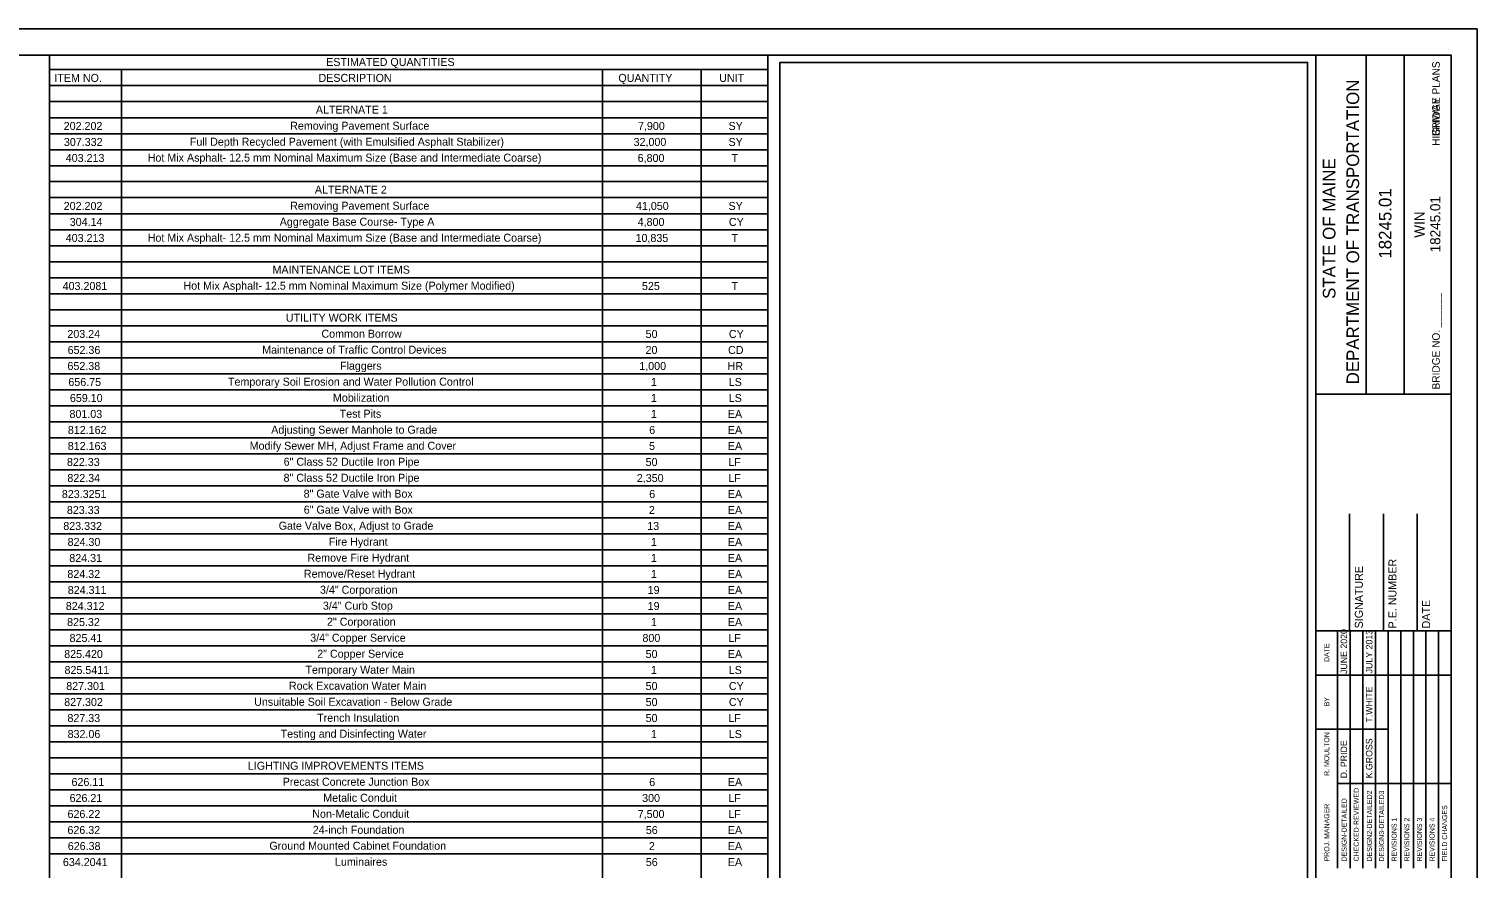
# Model space of a CAD drawing. Extents: x -0.13 to 2.7, y -0.05 to 1.78.
# Drawn here: x 0.917 to 2.698, y 0.75 to 1.782 of the extents above; entities that cross this region are included whole.
import ezdxf

# ---------------------------------------------------------------- set-up
doc = ezdxf.new("R2010")
doc.units = 0
for name, color, linetype in [('ANNOTATION', 7, 'Continuous'), ('BORDER', 7, 'Continuous'), ('BRIDGE_TITLE', 7, 'Continuous'), ('Default', 7, 'Continuous'), ('HIGHWAY_TITLE', 7, 'Continuous'), ('PLOT BOUNDARY', 7, 'Continuous')]:
    doc.layers.add(name, color=color, linetype=linetype)

msp = doc.modelspace()

# ---------------------------------------------------------------- linework, layer by layer
at = {"layer": 'BORDER'}
for p, q in [((2.5, 0), (2.5, 1.75)), ((2.5621, 1.3333), (2.5621, 1.75)), ((2.6087, 1.3333), (2.6087, 1.75)), ((0.9428, 1.7323), (1.8261, 1.7323)), ((1.0314, 1.7323), (1.0314, 0)), ((1.6227, 1.7323), (1.6227, 0)), ((1.7441, 1.7323), (1.7441, 0)), ((0.9428, 1.7126), (1.8261, 1.7126)), ((0.9428, 1.6929), (1.8261, 1.6929)), ((0.9428, 1.6732), (1.8261, 1.6732)), ((0.9428, 1.6535), (1.8261, 1.6535)), ((0.9428, 1.6338), (1.8261, 1.6338)), ((0.9428, 1.6141), (1.8261, 1.6141)), ((0.9428, 1.5945), (1.8261, 1.5945)), ((0.9428, 1.5748), (1.8261, 1.5748)), ((0.9428, 1.5551), (1.8261, 1.5551)), ((0.9428, 1.5354), (1.8261, 1.5354)), ((0.9428, 1.5157), (1.8261, 1.5157)), ((0.9428, 1.496), (1.8261, 1.496)), ((0.9428, 1.4763), (1.8261, 1.4763)), ((0.9428, 1.4566), (1.8261, 1.4566)), ((0.9428, 1.437), (1.8261, 1.437)), ((0.9428, 1.4173), (1.8261, 1.4173)), ((0.9428, 1.3976), (1.8261, 1.3976)), ((0.9428, 1.3779), (1.8261, 1.3779)), ((0.9428, 1.3582), (1.8261, 1.3582)), ((0.9428, 1.3385), (1.8261, 1.3385)), ((0.9428, 1.3188), (1.8261, 1.3188)), ((2.5, 1.3332), (2.6667, 1.3332)), ((0.9428, 1.2992), (1.8261, 1.2992)), ((0.9428, 1.2795), (1.8261, 1.2795)), ((0.9428, 1.2598), (1.8261, 1.2598)), ((0.9428, 1.2401), (1.8261, 1.2401)), ((0.9428, 1.2204), (1.8261, 1.2204)), ((0.9428, 1.2007), (1.8261, 1.2007)), ((0.9428, 1.181), (1.8261, 1.181)), ((2.5417, 1.0417), (2.5417, 1.1858)), ((2.5833, 1.0417), (2.5833, 1.1858)), ((2.625, 1.0417), (2.625, 1.1858)), ((0.9428, 1.1614), (1.8261, 1.1614)), ((0.9428, 1.1417), (1.8261, 1.1417)), ((0.9428, 1.122), (1.8261, 1.122)), ((0.9428, 1.1023), (1.8261, 1.1023)), ((0.9428, 1.0826), (1.8261, 1.0826)), ((0.9428, 1.0629), (1.8261, 1.0629)), ((0.9428, 1.0432), (1.8261, 1.0432)), ((2.5, 1.0417), (2.6667, 1.0417)), ((0.9428, 1.0236), (1.8261, 1.0236)), ((0.9428, 1.0039), (1.8261, 1.0039)), ((0.9428, 0.9842), (1.8261, 0.9842)), ((0.9428, 0.9645), (1.8261, 0.9645)), ((0.9428, 0.9448), (1.8261, 0.9448)), ((0.9428, 0.9251), (1.8261, 0.9251)), ((0.9428, 0.9054), (1.8261, 0.9054)), ((0.9428, 0.8858), (1.8261, 0.8858)), ((0.9428, 0.8661), (1.8261, 0.8661)), ((0.9428, 0.8464), (1.8261, 0.8464)), ((0.9428, 0.8267), (1.8261, 0.8267)), ((0.9428, 0.807), (1.8261, 0.807)), ((0.9428, 0.7873), (1.8261, 0.7873)), ((0.9428, 0.7676), (1.8261, 0.7676))]:
    msp.add_line(p, q, dxfattribs=at)
msp.add_lwpolyline([(0, 1.75), (2.6667, 1.75), (2.6667, 0), (0, 0)], close=True, dxfattribs=at)
for points in [[(0.9428, 0), (0.9428, 1.75)], [(1.8261, 1.75), (1.8261, 0)], [(2.5269, 0.9875), (2.5269, 1.0417)], [(2.5425, 0.7501), (2.5425, 1.0417)], [(2.558, 1.0417), (2.558, 0.7501)], [(2.5735, 0.7501), (2.5735, 1.0417)], [(2.589, 0.7501), (2.589, 1.0417)], [(2.6046, 0.7501), (2.6046, 1.0417)], [(2.6201, 0.7501), (2.6201, 1.0417)], [(2.6356, 0.7501), (2.6356, 1.0417)], [(2.6512, 0.7501), (2.6512, 1.0417)], [(2.5269, 0.7501), (2.5269, 1.0299)], [(2.5, 0.9875), (2.6667, 0.9875)], [(2.5, 0.9209), (2.5269, 0.9209)], [(2.5269, 0.9209), (2.589, 0.9209)], [(2.5269, 0.8542), (2.6667, 0.8542)]]:
    msp.add_lwpolyline(points, dxfattribs=at)
at = {"layer": 'Default'}
msp.add_lwpolyline([(1.841, 0.5306), (2.49, 0.5306), (2.49, 1.7412), (1.841, 1.7412)], close=True, dxfattribs=at)
at = {"layer": 'PLOT BOUNDARY'}
msp.add_lwpolyline([(-0.1349, -0.051), (2.6984, -0.051), (2.6984, 1.7823), (-0.1349, 1.7823)], close=True, dxfattribs=at)

# ---------------------------------------------------------------- texts
at = {"layer": 'ANNOTATION'}
for s, height, p in [('202.202', 0.00984, (0.9602, 1.6581)), ('Removing Pavement Surface', 0.009843, (1.2387, 1.6584)), ('7,900', 0.00984, (1.6665, 1.6581)), ('SY', 0.00984, (1.7779, 1.6581)), ('307.332', 0.00984, (0.9604, 1.6384)), ('Full Depth Recycled Pavement (with Emulsified Asphalt Stabilizer)', 0.009843, (1.1154, 1.6387)), ('32,000', 0.00984, (1.6611, 1.6384)), ('SY', 0.00984, (1.7779, 1.6384)), ('403.213', 0.00984, (0.9627, 1.6187)), ('Hot Mix Asphalt- 12.5 mm Nominal Maximum Size (Base and Intermediate Coarse)', 0.009843, (1.0635, 1.6191)), ('6,800', 0.00984, (1.6661, 1.6187)), ('T', 0.00984, (1.7815, 1.6187)), ('202.202', 0.00984, (0.9602, 1.5597)), ('Removing Pavement Surface', 0.009843, (1.2387, 1.56)), ('41,050', 0.00984, (1.664, 1.5597)), ('SY', 0.00984, (1.7779, 1.5597)), ('304.14', 0.00984, (0.9676, 1.54)), ('Aggregate Base Course- Type A', 0.009843, (1.2259, 1.5403)), ('4,800', 0.00984, (1.6661, 1.54)), ('CY', 0.00984, (1.7783, 1.54)), ('403.213', 0.00984, (0.9627, 1.5203)), ('Hot Mix Asphalt- 12.5 mm Nominal Maximum Size (Base and Intermediate Coarse)', 0.009843, (1.0635, 1.5206)), ('10,835', 0.00984, (1.6635, 1.5203)), ('T', 0.00984, (1.7815, 1.5203)), ('403.2081', 0.00984, (0.9589, 1.4612)), ('Hot Mix Asphalt- 12.5 mm Nominal Maximum Size (Polymer Modified)', 0.009843, (1.1075, 1.4616)), ('525', 0.00984, (1.6714, 1.4612)), ('T', 0.00984, (1.7815, 1.4612)), ('203.24', 0.00984, (0.9647, 1.4022)), ('Common Borrow', 0.009843, (1.2772, 1.4025)), ('50', 0.00984, (1.6759, 1.4022)), ('CY', 0.00984, (1.7783, 1.4022)), ('652.36', 0.00984, (0.965, 1.3825)), ('Maintenance of Traffic Control Devices', 0.009843, (1.2043, 1.3828)), ('20', 0.00984, (1.6758, 1.3825)), ('CD', 0.00984, (1.7773, 1.3825)), ('652.38', 0.00984, (0.9648, 1.3628)), ('Flaggers', 0.00984, (1.3, 1.3631)), ('1,000', 0.00984, (1.6681, 1.3628)), ('HR', 0.00984, (1.7767, 1.3628)), ('Temporary Soil Erosion and Water Pollution Control', 0.009843, (1.1622, 1.3435)), ('656.75', 0.00984, (0.9659, 1.3431)), ('1', 0.00984, (1.6824, 1.3431)), ('LS', 0.00984, (1.7781, 1.3431)), ('659.10', 0.00984, (0.9678, 1.3234)), ('Mobilization', 0.009843, (1.2913, 1.3238)), ('1', 0.00984, (1.6824, 1.3234)), ('LS', 0.00984, (1.7781, 1.3234)), ('801.03', 0.00984, (0.9673, 1.3038)), ('Test Pits', 0.00984, (1.2996, 1.3041)), ('1', 0.00984, (1.6824, 1.3038)), ('EA', 0.00984, (1.777, 1.3038)), ('812.162', 0.00984, (0.9653, 1.2841)), ('Adjusting Sewer Manhole to Grade', 0.009843, (1.2154, 1.2844)), ('6', 0.00984, (1.6803, 1.2841)), ('EA', 0.00984, (1.777, 1.2841)), ('812.163', 0.00984, (0.9652, 1.2644)), ('Modify Sewer MH, Adjust Frame and Cover', 0.009843, (1.1889, 1.2647)), ('5', 0.00984, (1.6801, 1.2644)), ('EA', 0.00984, (1.777, 1.2644)), ('822.33', 0.00984, (0.9642, 1.2447)), ('6" Class 52 Ductile Iron Pipe', 0.009843, (1.2307, 1.245)), ('50', 0.00984, (1.6759, 1.2447)), ('LF', 0.00984, (1.7776, 1.2447)), ('822.34', 0.00984, (0.9647, 1.225)), ('8" Class 52 Ductile Iron Pipe', 0.009843, (1.2306, 1.2253)), ('2,350', 0.00984, (1.6651, 1.225)), ('LF', 0.00984, (1.7776, 1.225)), ('823.3251', 0.00984, (0.9579, 1.2053)), ('8" Gate Valve with Box', 0.009843, (1.2553, 1.2057)), ('6', 0.00984, (1.6803, 1.2053)), ('EA', 0.00984, (1.777, 1.2053)), ('823.33', 0.00984, (0.9641, 1.1856)), ('6" Gate Valve with Box', 0.009843, (1.2554, 1.186)), ('2', 0.00984, (1.6799, 1.1856)), ('EA', 0.00984, (1.777, 1.1856)), ('823.332', 0.00984, (0.9597, 1.166)), ('Gate Valve Box, Adjust to Grade', 0.009843, (1.2246, 1.1663)), ('13', 0.00984, (1.6779, 1.166)), ('EA', 0.00984, (1.777, 1.166)), ('824.30', 0.00984, (0.965, 1.1463)), ('Fire Hydrant', 0.009843, (1.2862, 1.1466)), ('1', 0.00984, (1.6824, 1.1463)), ('EA', 0.00984, (1.777, 1.1463)), ('824.31', 0.00984, (0.9671, 1.1266)), ('Remove Fire Hydrant', 0.009843, (1.26, 1.1269)), ('1', 0.00984, (1.6824, 1.1266)), ('EA', 0.00984, (1.777, 1.1266)), ('824.32', 0.00984, (0.9647, 1.1069)), ('Remove/Reset Hydrant', 0.009843, (1.2556, 1.1072)), ('1', 0.00984, (1.6824, 1.1069)), ('EA', 0.00984, (1.777, 1.1069)), ('824.311', 0.00984, (0.9652, 1.0872)), ('3/4" Corporation', 0.009843, (1.2754, 1.0875)), ('19', 0.00984, (1.6784, 1.0872)), ('EA', 0.00984, (1.777, 1.0872)), ('824.312', 0.00984, (0.9628, 1.0675)), ('3/4" Curb Stop', 0.009843, (1.279, 1.0679)), ('19', 0.00984, (1.6784, 1.0675)), ('EA', 0.00984, (1.777, 1.0675)), ('825.32', 0.00984, (0.9644, 1.0478)), ('2" Corporation', 0.009843, (1.284, 1.0482)), ('1', 0.00984, (1.6824, 1.0478)), ('EA', 0.00984, (1.777, 1.0478)), ('825.41', 0.00984, (0.9674, 1.0282)), ('3/4" Copper Service', 0.009843, (1.2634, 1.0285)), ('800', 0.00984, (1.672, 1.0282)), ('LF', 0.00984, (1.7776, 1.0282)), ('825.420', 0.00984, (0.9608, 1.0085)), ('2" Copper Service', 0.009843, (1.272, 1.0088)), ('50', 0.00984, (1.6759, 1.0085)), ('EA', 0.00984, (1.777, 1.0085)), ('825.5411', 0.00984, (0.9612, 0.9888)), ('Temporary Water Main', 0.009843, (1.2575, 0.9891)), ('1', 0.00984, (1.6824, 0.9888)), ('LS', 0.00984, (1.7781, 0.9888)), ('Rock Excavation Water Main', 0.009843, (1.2372, 0.9694)), ('827.301', 0.00984, (0.9633, 0.9691)), ('50', 0.00984, (1.6759, 0.9691)), ('CY', 0.00984, (1.7783, 0.9691)), ('827.302', 0.00984, (0.9608, 0.9494)), ('Unsuitable Soil Excavation - Below Grade', 0.009843, (1.1944, 0.9497)), ('50', 0.00984, (1.6759, 0.9494)), ('CY', 0.00984, (1.7783, 0.9494)), ('827.33', 0.00984, (0.9648, 0.9297)), ('Trench Insulation', 0.009843, (1.2719, 0.93)), ('50', 0.00984, (1.6759, 0.9297)), ('LF', 0.00984, (1.7776, 0.9297)), ('832.06', 0.00984, (0.965, 0.91)), ('Testing and Disinfecting Water', 0.009843, (1.227, 0.9104)), ('1', 0.00984, (1.6824, 0.91)), ('LS', 0.00984, (1.7781, 0.91)), ('626.11', 0.00984, (0.9698, 0.851)), ('Precast Concrete Junction Box', 0.009843, (1.2295, 0.8513)), ('6', 0.00984, (1.6803, 0.851)), ('EA', 0.00984, (1.777, 0.851)), ('626.21', 0.00984, (0.9674, 0.8313)), ('Metalic Conduit', 0.009843, (1.2794, 0.8316)), ('300', 0.00984, (1.6716, 0.8313)), ('LF', 0.00984, (1.7776, 0.8313)), ('626.22', 0.00984, (0.9649, 0.8116)), ('Non-Metalic Conduit', 0.009843, (1.2659, 0.8119)), ('7,500', 0.00984, (1.6662, 0.8116)), ('LF', 0.00984, (1.7776, 0.8116)), ('626.32', 0.00984, (0.9648, 0.7919)), ('24-inch Foundation', 0.009843, (1.2665, 0.7922)), ('56', 0.00984, (1.6761, 0.7919)), ('EA', 0.00984, (1.777, 0.7919)), ('626.38', 0.00984, (0.9652, 0.7722)), ('Ground Mounted Cabinet Foundation ', 0.009843, (1.2132, 0.7726)), ('2', 0.00984, (1.6799, 0.7722)), ('EA', 0.00984, (1.777, 0.7722)), ('634.2041', 0.00984, (0.9592, 0.7525)), ('Luminaires', 0.00984, (1.2938, 0.7529)), ('56', 0.00984, (1.6761, 0.7525)), ('EA', 0.00984, (1.777, 0.7525))]:
    msp.add_text(s, height=height, dxfattribs=at).set_placement(p)
at = {"layer": 'BORDER'}
for s, height, p in [('ESTIMATED QUANTITIES', 0.009843, (1.283, 1.7368)), ('ITEM NO.', 0.00984, (0.9487, 1.7172)), ('DESCRIPTION', 0.009843, (1.2736, 1.7172)), ('QUANTITY', 0.00984, (1.6424, 1.7172)), ('UNIT', 0.00984, (1.7664, 1.7172)), ('ALTERNATE 1', 0.009843, (1.2703, 1.6781)), ('ALTERNATE 2', 0.009843, (1.2691, 1.5797)), ('MAINTENANCE LOT ITEMS', 0.009843, (1.217, 1.4813)), ('UTILITY WORK ITEMS', 0.009843, (1.2334, 1.4222)), ('LIGHTING IMPROVEMENTS ITEMS', 0.009843, (1.1867, 0.871))]:
    msp.add_text(s, height=height, dxfattribs=at).set_placement(p)
for s, height, p in [('DEPARTMENT OF TRANSPORTATION', 0.015529, (2.5534, 1.3451)), ('STATE OF MAINE', 0.015529, (2.5243, 1.4502)), ('18245.01', 0.01553, (2.5932, 1.4997)), ('18245.01', 0.01242, (2.6533, 1.5075)), ('WIN', 0.01242, (2.6339, 1.5255)), ('P.E. NUMBER', 0.009843, (2.5993, 1.0449)), ('SIGNATURE', 0.00984, (2.558, 1.0449)), ('DATE', 0.00984, (2.6407, 1.0449)), ('JUNE 2020', 0.00808, (2.5387, 0.9888)), ('JULY 2013', 0.00808, (2.5698, 0.9896)), ('DATE', 0.00619, (2.5167, 1.0035)), ('T.WHITE', 0.00808, (2.5698, 0.929)), ('BY', 0.00619, (2.5167, 0.949)), ('R. MOULTON', 0.00621, (2.5167, 0.8634)), ('K.GROSS', 0.00808, (2.5698, 0.8604)), ('D. PRIDE', 0.00808, (2.5387, 0.8604)), ('CHECKED-REVIEWED', 0.006212, (2.553, 0.7582)), ('DESIGN2-DETAILED2', 0.006212, (2.5692, 0.7582)), ('DESIGN3-DETAILED3', 0.006212, (2.5841, 0.7582)), ('PROJ. MANAGER', 0.006212, (2.5167, 0.7582)), ('DESIGN-DETAILED', 0.006212, (2.5381, 0.7582)), ('FIELD CHANGES', 0.006212, (2.6617, 0.7582)), ('REVISIONS 1', 0.006212, (2.5996, 0.7582)), ('REVISIONS 2', 0.006212, (2.6151, 0.7582)), ('REVISIONS 3', 0.006212, (2.6307, 0.7582)), ('REVISIONS 4', 0.006212, (2.6462, 0.7582))]:
    msp.add_text(s, height=height, rotation=90, dxfattribs=at).set_placement(p)
at = {"layer": 'BRIDGE_TITLE'}
for s, p in [('BRIDGE PLANS', (2.6526, 1.6504)), ('BRIDGE NO. ______', (2.6526, 1.3388))]:
    msp.add_text(s, height=0.009317, rotation=90, dxfattribs=at).set_placement(p)
at = {"layer": 'HIGHWAY_TITLE'}
msp.add_text('HIGHWAY PLANS', height=0.009317, rotation=90, dxfattribs=at).set_placement((2.6526, 1.6386))

doc.saveas('drawing.dxf')
